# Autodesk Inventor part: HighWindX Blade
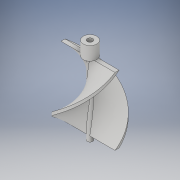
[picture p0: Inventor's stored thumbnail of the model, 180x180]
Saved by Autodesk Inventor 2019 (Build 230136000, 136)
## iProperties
Created: 2018-12
Part Number: HighWindX Blade
Material: Generic
Document SubType Name: Modeling
Designer: Patel Family
Density: 1 g/cm^3
Appearance: Default
Author: Patel Family
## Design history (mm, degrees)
sketch "Sketch1"
  geometry: L1 (-10, -0.75)-(10, -0.75); L2 (10, -0.75)-(10, 0.75); L3 (10, 0.75)-(-10, 0.75); L4 (-10, 0.75)-(-10, -0.75); L5 (-10, -0.75)-(10, 0.75); L6 (10, -0.75)-(-10, 0.75); 1 further point
  constraints: 12 end point, 2 midpoint, 2 parallel, 1 horizontal, 1 perpendicular
  dimensions: "d0" = 20 distance of L3.end L2.end; "d1" = 1.5 distance of L2.end L1.end
sketch "Sketch2"
  geometry: L1 (0, 0)-(0.727, 0)
  constraints: 2 end point, 1 horizontal
coil "Coil1" sketch "Sketch1", "Sketch2" pitch "d2" = 50; turns "d4" = 0.5; dims "d3" = 10, "d5" = 0, angle "d6" = 90 deg, angle "d7" = 90 deg, "d8" = 0, "d9" = 0
sketch "Sketch3"
  geometry: C1 r 2.5 at (10, -0.75); 1 further point
  constraints: 1 centre point, 1 coincident
  dimensions: "d10" = 5 diameter of C1
extrude "Extrusion1" join sketch "Sketch3" distance "d11" = 5; taper "d12" = 0 deg
sketch "Sketch4"
  geometry: C1 r 1 at (0, 0); 1 further point
  constraints: 1 centre point, 1 coincident
  dimensions: "d13" = 2 diameter of C1
extrude "Extrusion2" cut sketch "Sketch4" distance "d14" = 3; taper "d15" = 0 deg
sketch "Sketch5"
  geometry: C1 r 1 at (10, 0.75) reference; C2 r 1 at (10, 0.75); 1 further point
  constraints: 1 centre point, 1 coincident
extrude "Extrusion3" join sketch "Sketch5" distance "d16" = 27; taper "d17" = 0 deg
body "Solid1"
